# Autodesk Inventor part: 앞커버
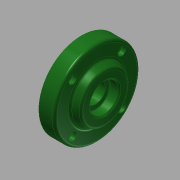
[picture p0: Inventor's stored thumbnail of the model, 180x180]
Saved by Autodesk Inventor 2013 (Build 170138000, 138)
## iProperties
Company: 한국ATC센터
Created: 2015-12
Part Number: 앞커버
Document SubType Name: Modeling
Designer: 앞커버
Density: 2.71 g/cm^3
Mass: 114.341 g
Surface Area: 117.908 cm^2
Volume: 42.1921 cm^3
Material: 알루미늄-6061
Author: mdu
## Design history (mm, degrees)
sketch "스케치1"
  geometry: L1 (-11.5, 0)-(11.5, 0); L2 (11.5, 0)-(11.5, 22.5); L3 (11.5, 22.5)-(6.5, 22.5); L4 (6.5, 22.5)-(6.5, 32.5); L5 (6.5, 32.5)-(-5.5, 32.5); L6 (-5.5, 32.5)-(-5.5, 21); L7 (-5.5, 21)-(-11.5, 18.202); L8 (-11.5, 18.202)-(-11.5, 0); 2 further points
  constraints: 16 end point, 3 parallel, 3 perpendicular, 1 coincident, 1 horizontal, 1 midpoint
  dimensions: "d0" = 23 distance of L1.start L1.end; "d1" = 65 diameter of L5 L1; "d2" = 45 diameter of L3 L1; "d3" = 42 diameter of L6.end L1; "d4" = 115 deg angle of L7 L6; "d5" = 12 distance of L4.end L5.end; "d6" = 5 distance of L2.end L3.end
revolve "회전1" sketch "스케치1" stored, may be unused: angle "d7" = 90 deg
sketch "스케치2"
  geometry: L1 (0, 0)-(32.5, 0); L2 (0, 0)-(18.738, 18.738); 1 further point
  constraints: 4 end point, 1 horizontal, 1 horizontal alignment, 1 other
  dimensions: "d8" = 45 deg angle of L1 L2; "d9" = 26.5 distance of L1.start L2.end
hole "구멍1" sketch "스케치2" at (18.738, 18.738) diameter "d10" = 3.4; stored, may be unused: countersink angle "d14" = 90 deg, drill point angle "d16" = 118 deg; dims "d11" = 6, "d12" = 6, "d13" = 3.3, "d15" = 8
fillet "모깎기1" dims "d20" = 2
hole "구멍2" diameter "d23" = 15; stored, may be unused: countersink angle "d27" = 90 deg, drill point angle "d29" = 118 deg; dims "d21" = 10, "d22" = 10, "d24" = 6, "d25" = 32, "d26" = 10, "d28" = 8
hole "구멍3" diameter "d32" = 22; stored, may be unused: countersink angle "d36" = 90 deg, drill point angle "d38" = 0 deg; dims "d30" = 10, "d31" = 10, "d33" = 6, "d34" = 32, "d35" = 10, "d37" = 7.3
chamfer "모따기1" distance "d39" = 1; stored, may be unused: second distance "d40" = 2, angle "d41" = 45 deg
fillet "모깎기2" dims "d42" = 0.3
node "작업 평면1"
sketch "스케치3"
  geometry: 2 further points
  constraints: 1 coincident, 1 other
feature "엠보싱1" sketch "스케치3" dims "d44" = 0.3, "d45" = 0
fillet "모깎기3" dims "d46" = 0.2
fillet "모깎기4" dims "d47" = 0.1
node "솔리드1"
pattern_circular "원형 패턴1" dims angle "d18" = 360 deg
